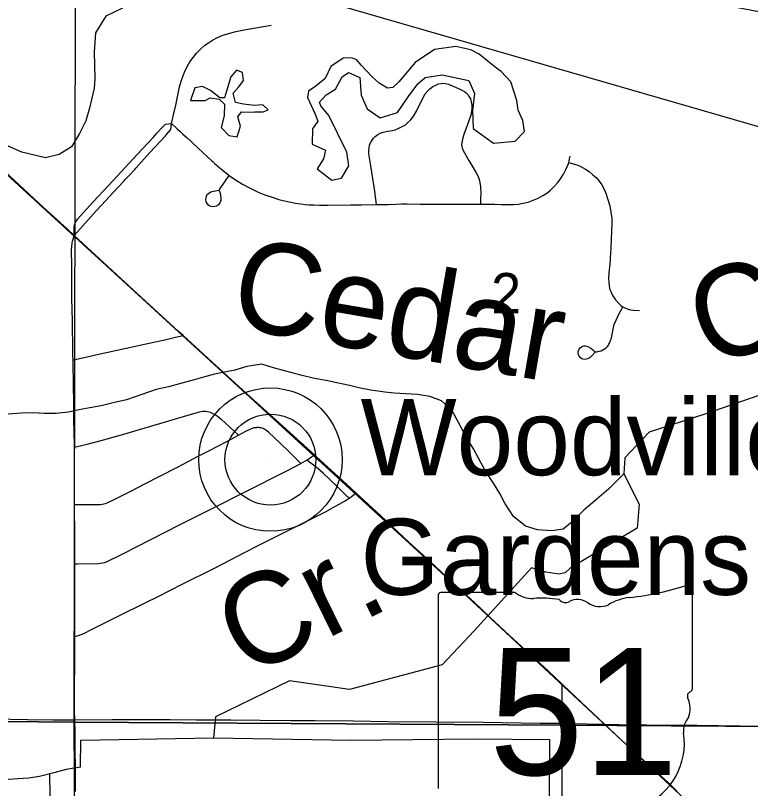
# Model space of a CAD drawing. Extents: x 0 to 34, y 0 to 22.
# Drawn here: x 2.63 to 3.392, y 19.337 to 20.14 of the extents above; entities that cross this region are included whole.
import ezdxf

# ---------------------------------------------------------------- set-up
doc = ezdxf.new("R2010")
doc.units = 0
for name, color, linetype in [('Default', 7, 'Continuous'), ('GM_X_County_Road', 7, 'Continuous'), ('GM_X_Minor_Lake', 7, 'Continuous'), ('GM_X_Minor_River', 7, 'Continuous'), ('GM_X_Minor_River_Text', 7, 'Continuous'), ('GM_X_Rail_Line', 7, 'Continuous'), ('GM_X_Section', 7, 'Continuous'), ('GM_X_Section_Text', 7, 'Continuous'), ('GM_X_State_Location', 7, 'Continuous'), ('GM_X_State_Route', 7, 'Continuous'), ('GM_X_State_Shield', 7, 'Continuous'), ('GM_X_Township_Road', 7, 'Continuous'), ('GM_X_Unincorporated', 7, 'Continuous'), ('GM_X_Unincorporated_Location', 7, 'Continuous'), ('GM_X_Unincorporated_Text', 7, 'Continuous'), ('SH_Text', 7, 'Continuous')]:
    doc.layers.add(name, color=color, linetype=linetype)

msp = doc.modelspace()

# ---------------------------------------------------------------- linework, layer by layer
at = {"layer": 'Default'}
for points in [[(2.1, 20.35368), (2.1, 19.41166), (2.69072, 19.40645), (2.6925, 20.35134)], [(2.1, 19.41166), (2.1, 18.40522), (2.69664, 18.40086), (2.69072, 19.40645)]]:
    msp.add_lwpolyline(points, close=True, dxfattribs=at)
at = {"layer": 'GM_X_County_Road'}
for points in [[(2.68958, 19.78207), (2.68947, 19.78689), (2.68933, 19.79999), (2.68911, 19.81289), (2.68889, 19.82528), (2.68874, 19.83173), (2.68844, 19.84853), (2.68828, 19.86222), (2.68831, 19.86781), (2.6883, 19.87278), (2.68818, 19.87963), (2.68801, 19.89591), (2.68829, 19.90002), (2.68872, 19.9032), (2.68914, 19.90547), (2.68978, 19.9076), (2.69087, 19.91123)], [(2.69102, 19.69155), (2.69064, 19.70983), (2.69049, 19.71739), (2.69033, 19.73168), (2.68997, 19.7616), (2.68976, 19.77391), (2.68958, 19.78207)], [(2.69107, 19.6321), (2.69095, 19.65328), (2.69094, 19.66632), (2.69107, 19.68906), (2.69102, 19.69155)], [(2.69151, 19.57057), (2.69146, 19.58209), (2.69138, 19.58798), (2.69131, 19.602), (2.6911, 19.62717), (2.69107, 19.6321)], [(2.69133, 19.49504), (2.69133, 19.49866), (2.69135, 19.50814), (2.69126, 19.52132), (2.69141, 19.53803), (2.69143, 19.54285), (2.69148, 19.5493), (2.69156, 19.56187), (2.69151, 19.57057)], [(2.69131, 19.40885), (2.69111, 19.41835), (2.69118, 19.43401), (2.69119, 19.44212), (2.69128, 19.46756), (2.69131, 19.47814), (2.69133, 19.49504)], [(2.69207, 19.3342), (2.69207, 19.35509), (2.69197, 19.36469), (2.69182, 19.37234), (2.69175, 19.37871), (2.6916, 19.39508), (2.69131, 19.40885)]]:
    msp.add_lwpolyline(points, dxfattribs=at)
at = {"layer": 'GM_X_Minor_Lake'}
for p, q in [((3.14983, 20.05125), (3.14354, 20.07064)), ((2.87253, 20.03941), (2.8782, 20.03975))]:
    msp.add_line(p, q, dxfattribs=at)
for points in [[(3.14354, 20.07064), (3.13378, 20.08133), (3.12888, 20.08477), (3.12023, 20.09166), (3.11083, 20.09931), (3.10216, 20.10392), (3.08668, 20.10743), (3.06434, 20.10416), (3.04458, 20.09063), (3.02743, 20.07064), (3.02134, 20.06499), (3.01566, 20.06427), (3.007, 20.06926), (2.99948, 20.07613), (2.98859, 20.08796), (2.98409, 20.09368), (2.97881, 20.09562), (2.96973, 20.0953), (2.95681, 20.08666), (2.95105, 20.07417), (2.94154, 20.06627), (2.93395, 20.06101), (2.93277, 20.05456), (2.94059, 20.03706), (2.94357, 20.02984), (2.93784, 20.02191), (2.93773, 20.00598), (2.95131, 19.99982), (2.94935, 19.99073), (2.94286, 19.98052), (2.9579, 19.96866), (2.96813, 19.97087), (2.97578, 19.98372), (2.97361, 19.99777), (2.96391, 20.01756), (2.95495, 20.03583), (2.9467, 20.04575), (2.94522, 20.04955), (2.95207, 20.05709), (2.96195, 20.0631), (2.96884, 20.07595), (2.9753, 20.08046), (2.98699, 20.07508), (2.98838, 20.05686), (2.99471, 20.04278), (3.00826, 20.03321), (3.02608, 20.03878), (3.03716, 20.05502), (3.04708, 20.06861), (3.05469, 20.07539), (3.07249, 20.07793), (3.10005, 20.07206), (3.10601, 20.05875), (3.104, 20.04093), (3.10463, 20.02234), (3.12571, 20.00702), (3.14804, 20.00916), (3.15794, 20.01933), (3.15613, 20.03073), (3.15128, 20.04138), (3.14983, 20.05125)], [(2.8782, 20.03975), (2.8869, 20.03969), (2.89183, 20.04155), (2.88657, 20.0469), (2.87749, 20.0462), (2.86653, 20.04741), (2.85822, 20.04936), (2.85564, 20.05886), (2.86136, 20.06566), (2.86632, 20.07207), (2.86524, 20.08042), (2.85921, 20.08274), (2.85311, 20.07595), (2.84885, 20.06118), (2.84653, 20.05399), (2.84199, 20.05402), (2.83221, 20.06167), (2.82392, 20.0659), (2.81597, 20.06443), (2.81134, 20.05119), (2.82647, 20.05147), (2.83178, 20.05409), (2.84123, 20.05289), (2.84649, 20.04754), (2.84641, 20.0354), (2.8433, 20.02328), (2.85118, 20.01488), (2.85987, 20.01369), (2.86335, 20.02467), (2.86039, 20.03455), (2.86421, 20.03946), (2.87253, 20.03941)]]:
    msp.add_lwpolyline(points, dxfattribs=at)
at = {"layer": 'GM_X_Minor_River'}
for points in [[(2.74071, 20.1473), (2.72355, 20.13884), (2.71268, 20.12157), (2.71161, 20.10148), (2.71231, 20.07415), (2.71139, 20.0643), (2.70652, 20.04351), (2.70291, 20.03029), (2.69627, 20.01712), (2.68811, 20.00321), (2.67512, 19.99545), (2.66106, 19.99189), (2.63656, 19.99759), (2.62229, 20.0039)], [(3.26078, 19.66389), (3.24502, 19.64821), (3.23275, 19.63779), (3.21933, 19.62624), (3.20741, 19.61429), (3.19783, 19.60648), (3.18607, 19.60477), (3.17134, 19.60577), (3.15892, 19.60976), (3.14659, 19.61983), (3.13736, 19.63363), (3.13222, 19.64358), (3.12557, 19.65431), (3.11708, 19.66735), (3.1101, 19.68036), (3.10495, 19.68993), (3.09611, 19.70487), (3.08913, 19.71788), (3.08252, 19.73013), (3.0717, 19.73979), (3.05966, 19.74416), (3.04683, 19.74626), (3.03436, 19.74684), (3.02264, 19.74779), (3.01282, 19.74871), (2.99848, 19.75084), (2.98604, 19.75331), (2.97624, 19.75575), (2.96304, 19.75823), (2.9521, 19.76069), (2.94003, 19.76278), (2.92571, 19.76642), (2.91027, 19.77047), (2.89746, 19.77409), (2.88541, 19.7777), (2.86986, 19.77529), (2.85732, 19.7717), (2.8467, 19.7696), (2.83645, 19.76749), (2.82505, 19.76426), (2.81517, 19.76138), (2.78857, 19.75422), (2.77566, 19.75139), (2.76083, 19.74632), (2.74485, 19.74089), (2.73118, 19.73769), (2.71865, 19.73448), (2.70689, 19.73239), (2.6955, 19.7303), (2.68487, 19.72782), (2.67199, 19.72651), (2.65951, 19.72671), (2.64854, 19.72726), (2.63606, 19.72709), (2.61825, 19.72548)], [(3.41004, 19.74837), (3.34499, 19.7259), (3.28719, 19.7071), (3.2618, 19.68057), (3.26078, 19.66389), (3.27693, 19.63252), (3.27464, 19.60752), (3.20514, 19.56614), (3.20014, 19.56129), (3.19331, 19.55988), (3.1801, 19.56199), (3.16504, 19.56641), (3.10574, 19.50097), (3.07228, 19.46584), (2.97615, 19.44007), (2.91425, 19.44904), (2.83725, 19.41196), (2.83539, 19.38998)], [(2.6972, 19.35959), (2.69764, 19.38766), (2.83539, 19.38998), (2.97797, 19.38769), (3.10549, 19.38904), (3.18378, 19.38816), (3.18315, 19.27624), (3.1815, 19.14802), (3.18123, 19.05961), (3.18124, 18.96437), (3.18093, 18.84902), (3.18094, 18.70559), (3.18124, 18.58036), (3.18181, 18.47258), (3.1818, 18.37581), (3.07363, 18.37718), (2.95486, 18.37834), (2.85047, 18.38002), (2.74265, 18.38024), (2.69235, 18.38106), (2.6737, 18.39768)], [(2.6972, 19.35959), (2.68241, 19.35717), (2.66949, 19.35358), (2.65468, 19.35003), (2.6433, 19.34831), (2.63231, 19.34735), (2.62247, 19.34675), (2.60695, 19.34625), (2.59067, 19.34575), (2.58008, 19.34592), (2.56986, 19.34533), (2.56002, 19.34511), (2.54411, 19.34384), (2.53239, 19.34441), (2.5218, 19.34459), (2.5116, 19.34551), (2.49905, 19.34154), (2.48649, 19.33681)], [(2.66526, 19.35257), (2.66809, 19.14568), (2.66858, 18.96126), (2.66981, 18.7996)]]:
    msp.add_lwpolyline(points, dxfattribs=at)
at = {"layer": 'GM_X_Rail_Line'}
msp.add_lwpolyline([(2.1, 20.45308), (2.55851, 20.03122), (3.08839, 19.54612), (3.69943, 18.97714), (4.17632, 18.54034), (4.70589, 18.05557)], dxfattribs=at)
at = {"layer": 'GM_X_Section'}
for points in [[(3.7003, 20.3485), (3.70416, 19.40015), (2.69072, 19.40645), (2.6925, 20.35134)], [(2.69072, 19.40645), (3.70416, 19.40015), (3.70319, 18.38855), (2.69664, 18.40086)]]:
    msp.add_lwpolyline(points, close=True, dxfattribs=at)
at = {"layer": 'GM_X_State_Route'}
for points in [[(3.31633, 19.33435), (3.30705, 19.34321), (3.28705, 19.3618), (3.26899, 19.37805), (3.2409, 19.40431), (3.20488, 19.43802), (3.19691, 19.4456), (3.18235, 19.45947), (3.16692, 19.47375), (3.14245, 19.49635), (3.12235, 19.51493), (3.10564, 19.53072), (3.08322, 19.55135), (3.06002, 19.57295), (3.038, 19.59309), (3.00841, 19.6206), (2.98335, 19.64384), (2.97332, 19.65315), (2.95727, 19.66785), (2.94253, 19.6812), (2.93992, 19.68357), (2.9071, 19.71338), (2.8697, 19.74711), (2.82938, 19.78409), (2.80381, 19.80739), (2.79859, 19.81215), (2.73928, 19.86661), (2.69087, 19.91123), (2.68334, 19.91818), (2.65857, 19.9408), (2.64891, 19.9496), (2.60337, 19.99192)], [(2.60337, 19.99192), (2.64891, 19.9496), (2.65857, 19.9408), (2.68334, 19.91818), (2.69087, 19.91123), (2.73928, 19.86661), (2.79859, 19.81215), (2.80381, 19.80739), (2.82938, 19.78409), (2.8697, 19.74711), (2.9071, 19.71338), (2.93992, 19.68357), (2.94253, 19.6812), (2.95727, 19.66785), (2.97332, 19.65315), (2.98335, 19.64384), (3.00841, 19.6206), (3.038, 19.59309), (3.06002, 19.57295), (3.08322, 19.55135), (3.10564, 19.53072), (3.12235, 19.51493), (3.14245, 19.49635), (3.16692, 19.47375), (3.18235, 19.45947), (3.19691, 19.4456), (3.20488, 19.43802), (3.2409, 19.40431), (3.26899, 19.37805), (3.28705, 19.3618), (3.30705, 19.34321), (3.31633, 19.33435)]]:
    msp.add_lwpolyline(points, dxfattribs=at)
at = {"layer": 'GM_X_State_Shield'}
for p, q in [((3.14811, 19.54099), (3.0709, 19.54099)), ((3.33197, 19.44127), (3.33197, 19.54595)), ((3.0683, 19.53755), (3.0683, 19.33743)), ((3.33194, 19.44129), (3.33197, 19.44127))]:
    msp.add_line(p, q, dxfattribs=at)
for centre, radius, start, end in [((3.23805, 19.81382), 0.27962, 275.84447, 288.90645), ((3.32904, 19.54639), 0.00294, 351.86209, 97.738), ((3.07132, 19.53797), 0.00305, 98.1301, 188.1301), ((3.1665, 19.56422), 0.02963, 231.61951, 271.11188), ((3.17632, 19.42864), 0.10636, 80.48669, 94.98827), ((3.20047, 19.53901), 0.00855, 219.79206, 297.10237), ((3.21302, 19.51588), 0.01777, 54.46668, 119.14113), ((3.27371, 19.47987), 0.05625, 97.34618, 120.76885), ((3.23596, 19.54761), 0.02138, 233.85621, 294.82819), ((3.33129, 19.43358), 0.00454, 107.94398, 210.33697), ((3.32884, 19.44086), 0.00314, 289.60381, 7.73413), ((3.30239, 19.42035), 0.02727, 340.03296, 23.64957), ((3.34248, 19.39746), 0.01984, 136.8065, 186.92959), ((3.25371, 19.38414), 0.06994, 292.30889, 8.98584)]:
    msp.add_arc(centre, radius, start, end, dxfattribs=at)
at = {"layer": 'GM_X_Township_Road'}
msp.add_line((2.78856, 20.02713), (2.79164, 20.02762), dxfattribs=at)
for points in [[(2.79164, 20.02762), (2.79423, 20.03774), (2.79625, 20.0465), (2.80004, 20.06546), (2.80163, 20.07155), (2.80327, 20.07629), (2.80396, 20.07801), (2.80511, 20.08093), (2.80798, 20.08653), (2.81083, 20.09143), (2.81412, 20.09607), (2.81775, 20.10043), (2.8217, 20.10449), (2.82641, 20.10867), (2.82995, 20.11134), (2.83427, 20.11399), (2.83931, 20.11658), (2.8451, 20.11906), (2.85105, 20.12105), (2.85712, 20.12266), (2.86692, 20.12465), (2.88716, 20.12828), (2.89505, 20.1295)], [(3.00422, 19.94329), (3.00357, 19.94859), (3.00251, 19.95718), (2.99831, 19.98356), (2.99644, 19.99592), (2.99634, 19.99915), (2.99664, 20.00236), (2.99721, 20.0049), (2.99811, 20.00736), (2.99966, 20.01023), (3.00124, 20.01232), (3.00311, 20.01416), (3.00575, 20.01606), (3.00804, 20.01729), (3.01107, 20.01841), (3.01603, 20.01956), (3.02093, 20.02024), (3.02377, 20.02107), (3.02826, 20.02294), (3.03084, 20.02447), (3.03428, 20.02616), (3.03687, 20.02863), (3.03983, 20.03147), (3.04328, 20.03616), (3.04575, 20.04035), (3.0526, 20.05457), (3.05498, 20.05833), (3.05741, 20.06131), (3.05978, 20.06351), (3.06291, 20.06576), (3.06571, 20.06734), (3.06872, 20.06853), (3.07129, 20.06913), (3.0733, 20.06925), (3.07591, 20.06899), (3.07906, 20.06822), (3.08378, 20.06638), (3.09005, 20.06352), (3.09565, 20.06062), (3.09726, 20.05941), (3.09909, 20.05751), (3.10054, 20.05532), (3.10167, 20.05297), (3.10264, 20.04982), (3.10318, 20.04654), (3.10329, 20.04319), (3.10302, 20.03987), (3.1022, 20.03608), (3.10023, 20.03011), (3.09493, 20.01607), (3.09355, 20.01138), (3.09289, 20.00784), (3.0926, 20.00551), (3.09268, 20.0038), (3.0931, 20.00218), (3.09435, 19.99949), (3.10014, 19.98923), (3.10769, 19.97632), (3.1097, 19.97236), (3.11086, 19.96939), (3.11163, 19.96627), (3.11219, 19.96185), (3.11242, 19.95493), (3.11225, 19.94992), (3.11204, 19.94377)], [(2.69087, 19.91123), (2.69057, 19.91902), (2.69115, 19.92262), (2.69231, 19.92552), (2.69449, 19.92854), (2.69989, 19.93476), (2.71032, 19.9463), (2.72656, 19.96342), (2.73549, 19.97293), (2.75617, 19.9953), (2.7725, 20.01311), (2.7768, 20.01769), (2.78192, 20.02349), (2.78548, 20.02663), (2.78856, 20.02713)], [(2.69087, 19.91123), (2.69953, 19.92097), (2.71402, 19.93725), (2.73682, 19.96182), (2.74221, 19.96781), (2.7439, 19.96956), (2.74773, 19.97349), (2.75356, 19.97983), (2.75482, 19.98119), (2.76938, 19.99726), (2.77481, 20.00323), (2.78538, 20.01459), (2.78663, 20.01593), (2.79091, 20.0212), (2.79164, 20.02762)], [(2.79164, 20.02762), (2.79765, 20.02205), (2.80034, 20.01951), (2.80349, 20.01659), (2.80762, 20.01283), (2.82491, 19.99676), (2.83318, 19.9892), (2.83452, 19.9879), (2.83588, 19.98664), (2.83625, 19.98609), (2.83728, 19.98541), (2.83868, 19.98418), (2.83909, 19.98369), (2.84008, 19.98296), (2.84149, 19.98175), (2.84193, 19.9813), (2.84244, 19.98095), (2.84339, 19.98015), (2.84432, 19.97933), (2.84625, 19.97778), (2.84864, 19.97582), (2.85163, 19.97338)], [(3.2037, 19.98703), (3.20409, 19.98827), (3.20465, 19.99067), (3.20517, 19.99369)], [(3.11204, 19.94377), (3.11401, 19.9438), (3.1169, 19.94385), (3.12714, 19.94372), (3.13396, 19.94349), (3.1393, 19.94356), (3.14656, 19.94343), (3.15146, 19.94393), (3.15449, 19.94439), (3.15629, 19.94471), (3.15806, 19.94508), (3.1616, 19.94603), (3.16683, 19.94779), (3.17191, 19.95), (3.17679, 19.95264), (3.1809, 19.95534), (3.18474, 19.95839), (3.18872, 19.96219), (3.19239, 19.96631), (3.19534, 19.97022), (3.19829, 19.97489), (3.20087, 19.97981), (3.20302, 19.98486), (3.2037, 19.98703)], [(3.2037, 19.98703), (3.20923, 19.98543), (3.21218, 19.98457), (3.21571, 19.98307), (3.22125, 19.98004), (3.22494, 19.97758), (3.22888, 19.97439), (3.23207, 19.97131), (3.23538, 19.9675), (3.238, 19.96388), (3.24016, 19.95999), (3.24218, 19.95534), (3.24439, 19.9488), (3.2462, 19.94213), (3.24749, 19.93534), (3.24828, 19.9291), (3.24845, 19.92405), (3.24821, 19.91591), (3.24786, 19.9076), (3.24737, 19.89884), (3.247, 19.89255), (3.24676, 19.88835), (3.24663, 19.88613), (3.24627, 19.88144), (3.2454, 19.87268), (3.24504, 19.86651), (3.24516, 19.86331), (3.24578, 19.85886), (3.24652, 19.85541), (3.24763, 19.85245), (3.24887, 19.84961), (3.2522, 19.84455), (3.2559, 19.84036), (3.25813, 19.83839), (3.25988, 19.83731)], [(2.84108, 19.95793), (2.84207, 19.95514), (2.84256, 19.9528), (2.84281, 19.95033), (2.84269, 19.94749), (2.84195, 19.94502), (2.84047, 19.94305), (2.83837, 19.94156), (2.83647, 19.94123), (2.83455, 19.94119), (2.83282, 19.94144), (2.83158, 19.94181), (2.83023, 19.9428), (2.82862, 19.94452), (2.82764, 19.94637), (2.82739, 19.94835), (2.82763, 19.95032), (2.828, 19.95205), (2.82862, 19.95365), (2.82997, 19.95501), (2.83245, 19.95649), (2.83528, 19.95723), (2.83738, 19.9576), (2.84083, 19.95834), (2.8417, 19.95933), (2.8429, 19.96095), (2.8454, 19.96454), (2.84786, 19.96804), (2.85163, 19.97338)], [(2.85163, 19.97338), (2.85803, 19.96887), (2.86544, 19.96438), (2.87254, 19.96058), (2.88144, 19.95629), (2.88834, 19.95363), (2.89594, 19.951), (2.903, 19.94876), (2.90896, 19.9472), (2.91378, 19.9462), (2.92044, 19.94499), (2.92595, 19.94421), (2.93023, 19.94361), (2.93423, 19.94324), (2.93928, 19.943), (2.9453, 19.94272), (2.95374, 19.94282), (2.97722, 19.94318), (2.98889, 19.94302), (3.00422, 19.94329)], [(3.00422, 19.94329), (3.00974, 19.94339), (3.01641, 19.94352), (3.02406, 19.94377), (3.0301, 19.94402), (3.03625, 19.94407), (3.04947, 19.94378), (3.05811, 19.94366), (3.06798, 19.94366), (3.07428, 19.94379), (3.07933, 19.94367), (3.08624, 19.94379), (3.10351, 19.94384), (3.10599, 19.94367), (3.11204, 19.94377)], [(3.22588, 19.78482), (3.22483, 19.78396), (3.2231, 19.78319), (3.22191, 19.78286), (3.22005, 19.78278), (3.21822, 19.78311), (3.21709, 19.7836), (3.2156, 19.78473), (3.21442, 19.78618), (3.21372, 19.7879), (3.21348, 19.78974), (3.21371, 19.79157), (3.21445, 19.79328), (3.21561, 19.79473), (3.21708, 19.79587), (3.21822, 19.79638), (3.21943, 19.79664), (3.22067, 19.79665), (3.2226, 19.79655), (3.22433, 19.79581), (3.22656, 19.79445), (3.22828, 19.79297), (3.22964, 19.79185), (3.23027, 19.79132), (3.23089, 19.79092), (3.23181, 19.79067), (3.23291, 19.79067), (3.23386, 19.79084), (3.23528, 19.79118), (3.23722, 19.79176), (3.23916, 19.79256), (3.24096, 19.79356), (3.2425, 19.79475), (3.24384, 19.79604), (3.24494, 19.79743), (3.24548, 19.79838), (3.24605, 19.79952), (3.24715, 19.80223), (3.24802, 19.80519), (3.24901, 19.81013), (3.24975, 19.81407), (3.25085, 19.81889), (3.25283, 19.82358), (3.25566, 19.82962), (3.25838, 19.83456), (3.25988, 19.83731)], [(3.25988, 19.83731), (3.26133, 19.83641), (3.26442, 19.83518), (3.26788, 19.83419), (3.27084, 19.83364), (3.27725, 19.83333)], [(2.68958, 19.78207), (2.69319, 19.78288), (2.70428, 19.78534), (2.71463, 19.78764), (2.76382, 19.7984), (2.78605, 19.8034), (2.79594, 19.80562), (2.80381, 19.80739)], [(3.23138, 19.79058), (3.22693, 19.78568), (3.22588, 19.78482)], [(2.69102, 19.69155), (2.69391, 19.69227), (2.70426, 19.69482), (2.7188, 19.69852), (2.73979, 19.70438), (2.8043, 19.72349), (2.8207, 19.7282), (2.82249, 19.72856), (2.8241, 19.72883), (2.82571, 19.72892), (2.82723, 19.72892), (2.82884, 19.72874), (2.83027, 19.72838), (2.83179, 19.72785), (2.83394, 19.72687), (2.83609, 19.72579), (2.83904, 19.724), (2.84333, 19.7207), (2.85682, 19.70832), (2.86132, 19.70418)], [(2.86132, 19.70418), (2.86891, 19.70808), (2.87401, 19.71068), (2.87585, 19.71145), (2.87665, 19.71173), (2.87746, 19.71193), (2.8782, 19.71205), (2.8791, 19.71208), (2.88012, 19.7121)], [(2.92578, 19.6747), (2.922, 19.67845), (2.91326, 19.68709), (2.90424, 19.69591), (2.8924, 19.70712), (2.89089, 19.70834), (2.88931, 19.70952), (2.88777, 19.71044), (2.88667, 19.711), (2.88551, 19.7114), (2.8845, 19.71165), (2.8834, 19.71185), (2.88234, 19.712), (2.88113, 19.7121), (2.88012, 19.7121)], [(2.69107, 19.6321), (2.69374, 19.63208), (2.70409, 19.63201), (2.71579, 19.63211), (2.71783, 19.6322), (2.71977, 19.6324), (2.72164, 19.63275), (2.72322, 19.63324), (2.72509, 19.63393), (2.73276, 19.63766), (2.74946, 19.64613), (2.76398, 19.65349), (2.77951, 19.66148), (2.7979, 19.67092), (2.81943, 19.68215), (2.8303, 19.68773), (2.84905, 19.69742), (2.86132, 19.70418)], [(2.92578, 19.6747), (2.9306, 19.67739), (2.93197, 19.67824)], [(2.93197, 19.67824), (2.93434, 19.67973), (2.93686, 19.68147), (2.93992, 19.68357)], [(2.97591, 19.63857), (2.97237, 19.64201), (2.96326, 19.65104), (2.94888, 19.66482), (2.94339, 19.66944), (2.93899, 19.67282), (2.93197, 19.67824)], [(2.69151, 19.57057), (2.69452, 19.57064), (2.71604, 19.5711), (2.7182, 19.57124), (2.72027, 19.57155), (2.72233, 19.57203), (2.7241, 19.57262), (2.7405, 19.58058), (2.80072, 19.61132), (2.83728, 19.62975), (2.86594, 19.64414), (2.91141, 19.66713), (2.92578, 19.6747)], [(2.69133, 19.49504), (2.6952, 19.49637), (2.69806, 19.49736), (2.70071, 19.49844), (2.70867, 19.50238), (2.73844, 19.51732), (2.76378, 19.52962), (2.77862, 19.53699), (2.8022, 19.54909), (2.83698, 19.56659), (2.86734, 19.58233), (2.8823, 19.58983), (2.91411, 19.60573), (2.95143, 19.62471), (2.96196, 19.6303), (2.96883, 19.63425), (2.97119, 19.63562), (2.97591, 19.63857)], [(2.97591, 19.63857), (2.97993, 19.64143), (2.98335, 19.64384)], [(3.19699, 19.4051), (3.197, 19.40831), (3.19694, 19.43406), (3.19691, 19.4456)], [(2.44089, 19.41099), (2.46231, 19.41088), (2.50457, 19.41051), (2.53254, 19.4105), (2.58277, 19.40983), (2.60701, 19.40975), (2.64243, 19.40917), (2.66853, 19.40882), (2.69131, 19.40885)], [(2.69131, 19.40885), (2.73006, 19.4089), (2.76923, 19.40914), (2.79038, 19.40907), (2.81774, 19.40887), (2.83452, 19.40869), (2.85317, 19.40864), (2.88364, 19.4083), (2.91596, 19.40792), (2.94083, 19.40787), (2.98063, 19.40756), (3.01605, 19.40697), (3.0658, 19.40665), (3.11491, 19.40624), (3.17396, 19.4052), (3.19699, 19.4051)], [(3.19696, 19.32934), (3.19699, 19.4051)], [(3.19699, 19.4051), (3.20442, 19.40508), (3.2409, 19.40431)], [(3.2409, 19.40431), (3.27083, 19.40369), (3.28452, 19.40365), (3.31063, 19.40331), (3.33674, 19.40316), (3.3815, 19.40259), (3.41008, 19.40206), (3.48428, 19.40124), (3.50666, 19.40086), (3.56188, 19.40019), (3.58052, 19.39999), (3.61783, 19.3995), (3.63035, 19.3993)]]:
    msp.add_lwpolyline(points, dxfattribs=at)
at = {"layer": 'GM_X_Unincorporated'}
for radius in [0.0744, 0.04716]:
    msp.add_circle((2.8943, 19.67872), radius, dxfattribs=at)
at = {"layer": 'GM_X_Unincorporated_Location'}
msp.add_line((2.8943, 19.67872), (2.8943, 19.67872), dxfattribs=at)
at = {"layer": 'SH_Text'}
msp.add_lwpolyline([(9.21814, 19.03459), (2.19045, 20.37443), (9.21814, 18.3428)], close=True, dxfattribs=at)

# ---------------------------------------------------------------- texts
at = {"layer": 'GM_X_Minor_River_Text'}
for s, height, rotation, p in [('Creek', 0.09476, 19.19546, (3.34887, 19.77384)), ('Cedar', 0.094758, 350.19543, (2.85021, 19.81686)), ('Cr.', 0.094761, 26.19367, (2.86929, 19.45148))]:
    msp.add_text(s, height=height, rotation=rotation, dxfattribs=at).set_placement(p)
at = {"layer": 'GM_X_Section_Text'}
msp.add_text('2', height=0.04186, rotation=0.00001, dxfattribs=at).set_placement((3.12322, 19.83049))
at = {"layer": 'GM_X_State_Location'}
for s in ['s', 'r']:
    msp.add_text(s, height=0.000189, dxfattribs=at).set_placement((3.19716, 19.42418))
msp.add_text('51', height=0.000189, rotation=0.00001, dxfattribs=at).set_placement((3.14947, 19.41041))
at = {"layer": 'GM_X_State_Shield'}
msp.add_text('51', height=0.131836, dxfattribs=at).set_placement((3.12101, 19.35154))
at = {"layer": 'GM_X_Unincorporated_Text'}
for s, p in [('Woodville', (2.9878, 19.66258)), ('Gardens', (2.9878, 19.53841))]:
    msp.add_text(s, height=0.078977, rotation=0.00001, dxfattribs=at).set_placement(p)

doc.saveas('drawing.dxf')
